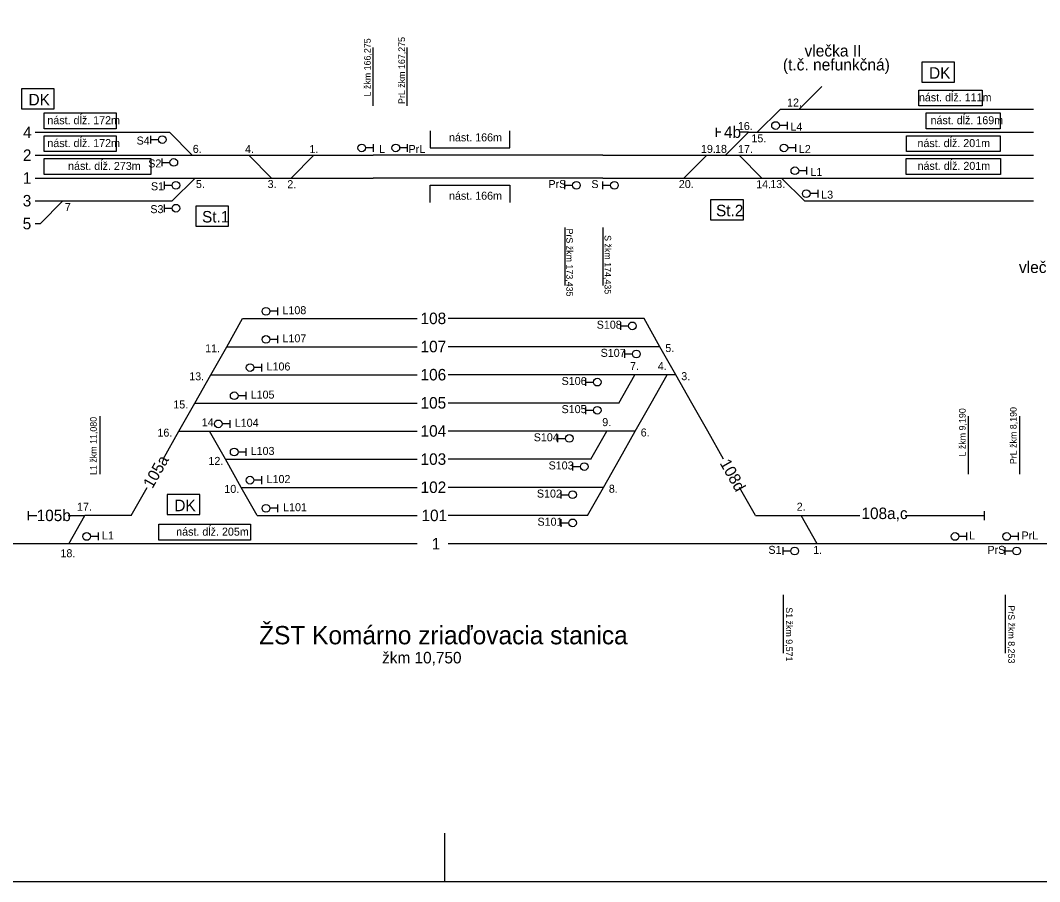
# Model space of a CAD drawing. Extents: x -119 to 851, y -238 to 59.
# Drawn here: x 243.9 to 333.1, y -238 to -162.7 of the extents above; entities that cross this region are included whole.
import ezdxf

# ---------------------------------------------------------------- set-up
doc = ezdxf.new("R2010")
doc.units = 0
for name, color, linetype in [('budova', 7, 'Continuous'), ('Level 2', 7, 'Continuous'), ('nastupistia', 7, 'Continuous'), ('netlač', 7, 'Continuous'), ('popisky navestidla', 7, 'Continuous'), ('popisky stanic a zastavok', 7, 'Continuous'), ('PU_navestidla', 7, 'Continuous'), ('PU_oznacenie navestidiel', 7, 'Continuous'), ('PU_stan_kolaje', 7, 'Continuous'), ('PU_vlecky', 7, 'Continuous')]:
    doc.layers.add(name, color=color, linetype=linetype)

msp = doc.modelspace()

# ---------------------------------------------------------------- linework, layer by layer
at = {"layer": 'budova'}
for points in [[(322.778, -168.11), (325.645, -168.11), (325.645, -166.362), (322.778, -166.362)], [(244.019, -170.441), (246.886, -170.441), (246.886, -168.693), (244.019, -168.693)], [(259.277, -180.699), (262.144, -180.699), (262.144, -178.951), (259.277, -178.951)], [(304.306, -180.156), (307.173, -180.156), (307.173, -178.408), (304.306, -178.408)], [(256.771, -205.924), (259.638, -205.924), (259.638, -204.176), (256.771, -204.176)]]:
    msp.add_lwpolyline(points, close=True, dxfattribs=at)
at = {"layer": 'Level 2'}
for p, q in [((332.55, -170.496), (310.376, -170.496)), ((332.17, -170.496), (331.948, -170.496)), ((245.232, -172.495), (256.972, -172.495)), ((304.823, -172.894), (304.823, -172.095)), ((305.192, -172.495), (304.823, -172.495)), ((307.616, -172.495), (306.853, -172.495)), ((307.616, -172.495), (332.55, -172.495)), ((245.232, -174.494), (252.131, -174.494)), ((252.131, -174.494), (274.8, -174.494)), ((294.882, -174.494), (301.378, -174.494)), ((301.378, -174.494), (317.575, -174.494)), ((317.575, -174.494), (332.55, -174.494)), ((245.232, -176.493), (253.131, -176.493)), ((253.131, -176.493), (271.429, -176.493)), ((271.429, -176.493), (274.8, -176.493)), ((294.882, -176.493), (316.376, -176.493)), ((316.376, -176.493), (332.55, -176.493)), ((245.232, -178.492), (257.207, -178.492)), ((312.507, -178.492), (332.55, -178.492)), ((245.65, -180.491), (245.232, -180.491)), ((244.601, -205.606), (244.601, -206.406)), ((328.225, -205.606), (328.225, -206.406)), ((244.601, -206.006), (245.382, -206.006)), ((248.098, -206.006), (249.564, -206.006)), ((278.636, -208.467), (236.419, -208.467)), ((360.51, -208.467), (281.352, -208.467))]:
    msp.add_line(p, q, dxfattribs=at)
at = {"layer": 'nastupistia'}
for points in [[(328.056, -170.184), (322.513, -170.184), (322.513, -168.799), (328.056, -168.799)], [(252.317, -172.183), (246.022, -172.183), (246.022, -170.798), (252.317, -170.798)], [(329.631, -172.183), (323.147, -172.183), (323.147, -170.798), (329.631, -170.798)], [(252.317, -174.182), (246.022, -174.182), (246.022, -172.797), (252.317, -172.797)], [(329.631, -174.182), (321.428, -174.182), (321.428, -172.797), (329.631, -172.797)], [(255.343, -176.181), (246.019, -176.181), (246.019, -174.796), (255.343, -174.796)], [(329.641, -176.171), (321.417, -176.171), (321.417, -174.786), (329.641, -174.786)], [(264.048, -208.155), (256.05, -208.155), (256.05, -206.77), (264.048, -206.77)]]:
    msp.add_lwpolyline(points, close=True, dxfattribs=at)
for points in [[(279.775, -172.355), (279.775, -173.859), (286.733, -173.859), (286.733, -172.355)], [(279.775, -178.632), (279.775, -177.129), (286.749, -177.129), (286.749, -178.632)]]:
    msp.add_lwpolyline(points, dxfattribs=at)
at = {"layer": 'netlač'}
for p, q in [((294.882, -174.494), (274.8, -174.494)), ((294.882, -176.493), (274.8, -176.493)), ((263.366, -188.78), (278.636, -188.78)), ((298.482, -188.78), (281.352, -188.78)), ((261.975, -191.241), (278.636, -191.241)), ((299.873, -191.241), (281.352, -191.241)), ((260.583, -193.702), (278.636, -193.702)), ((301.264, -193.702), (281.352, -193.702)), ((259.192, -196.162), (278.636, -196.162)), ((296.272, -196.162), (281.352, -196.162)), ((257.801, -198.623), (278.636, -198.623)), ((297.716, -198.623), (281.352, -198.623)), ((261.864, -201.084), (278.636, -201.084)), ((293.833, -201.084), (281.352, -201.084)), ((263.255, -203.545), (278.636, -203.545)), ((294.933, -203.545), (281.352, -203.545)), ((253.626, -206.006), (249.564, -206.006)), ((264.646, -206.006), (278.636, -206.006)), ((293.542, -206.006), (281.352, -206.006)), ((308.221, -206.006), (312.226, -206.006)), ((312.226, -206.006), (317.358, -206.006)), ((321.321, -206.006), (328.225, -206.006))]:
    msp.add_line(p, q, dxfattribs=at)
at = {"layer": 'popisky navestidla'}
for p, q in [((274.8, -170.181), (274.8, -165.091)), ((277.775, -170.181), (277.775, -165.091)), ((291.554, -180.806), (291.554, -185.897)), ((294.882, -180.806), (294.882, -185.897)), ((250.869, -197.303), (250.869, -202.394)), ((326.827, -197.303), (326.827, -202.394)), ((331.331, -197.303), (331.331, -202.394)), ((310.678, -218.037), (310.678, -212.946)), ((330.09, -218.037), (330.09, -212.946)), ((281.049, -238.008), (281.049, -233.772))]:
    msp.add_line(p, q, dxfattribs=at)
msp.add_lwpolyline([(-118.951, -238.008), (851.049, -238.008), (851.049, 58.992), (-118.951, 58.992)], close=True, dxfattribs=at)
at = {"layer": 'PU_navestidla'}
for p, q in [((310.988, -171.903), (310.316, -171.903)), ((310.988, -171.566), (310.988, -172.238)), ((255.331, -173.466), (255.331, -172.795)), ((255.331, -173.129), (256.003, -173.129)), ((274.8, -173.522), (274.8, -174.194)), ((277.775, -173.522), (277.775, -174.194)), ((311.722, -173.522), (311.722, -174.194)), ((274.8, -173.859), (274.128, -173.859)), ((277.775, -173.859), (277.103, -173.859)), ((311.722, -173.859), (311.05, -173.859)), ((256.344, -175.465), (256.344, -174.794)), ((256.344, -175.128), (257.016, -175.128)), ((312.677, -175.521), (312.677, -176.193)), ((312.677, -175.858), (312.005, -175.858)), ((256.53, -177.464), (256.53, -176.793)), ((256.53, -177.127), (257.202, -177.127)), ((291.554, -177.466), (291.554, -176.794)), ((291.554, -177.129), (292.226, -177.129)), ((294.882, -177.466), (294.882, -176.794)), ((294.882, -177.129), (295.554, -177.129)), ((313.676, -177.857), (313.004, -177.857)), ((313.676, -177.52), (313.676, -178.192)), ((256.531, -179.463), (256.531, -178.792)), ((256.531, -179.126), (257.203, -179.126)), ((266.423, -187.808), (266.423, -188.48)), ((266.423, -188.145), (265.751, -188.145)), ((296.452, -189.752), (296.452, -189.08)), ((296.452, -189.414), (297.124, -189.414)), ((266.423, -190.606), (265.751, -190.606)), ((266.423, -190.269), (266.423, -190.941)), ((296.793, -192.213), (296.793, -191.541)), ((296.793, -191.875), (297.465, -191.875)), ((265.031, -193.067), (264.359, -193.067)), ((265.031, -192.73), (265.031, -193.402)), ((293.38, -194.674), (293.38, -194.002)), ((263.64, -195.19), (263.64, -195.862)), ((293.38, -194.336), (294.052, -194.336)), ((263.64, -195.528), (262.968, -195.528)), ((293.38, -197.134), (293.38, -196.462)), ((293.38, -196.797), (294.052, -196.797)), ((262.248, -197.651), (262.248, -198.323)), ((262.248, -197.989), (261.576, -197.989)), ((290.94, -199.595), (290.94, -198.923)), ((290.94, -199.258), (291.612, -199.258)), ((263.64, -200.45), (262.968, -200.45)), ((263.64, -200.112), (263.64, -200.784)), ((292.242, -202.056), (292.242, -201.384)), ((292.242, -201.719), (292.914, -201.719)), ((265.031, -202.911), (264.359, -202.911)), ((265.031, -202.573), (265.031, -203.245)), ((291.218, -204.517), (291.218, -203.845)), ((291.218, -204.18), (291.89, -204.18)), ((266.423, -205.371), (265.751, -205.371)), ((266.423, -205.034), (266.423, -205.706)), ((291.218, -206.978), (291.218, -206.306)), ((291.218, -206.641), (291.89, -206.641)), ((250.736, -207.495), (250.736, -208.167)), ((326.694, -207.495), (326.694, -208.167)), ((331.198, -207.495), (331.198, -208.167)), ((250.736, -207.832), (250.064, -207.832)), ((326.694, -207.832), (326.022, -207.832)), ((331.198, -207.832), (330.526, -207.832)), ((310.649, -209.439), (310.649, -208.767)), ((310.649, -209.102), (311.321, -209.102)), ((330.061, -209.439), (330.061, -208.767)), ((330.061, -209.102), (330.733, -209.102))]:
    msp.add_line(p, q, dxfattribs=at)
for centre in [(309.98, -171.902), (256.339, -173.131), (273.792, -173.857), (276.767, -173.857), (310.714, -173.857), (257.352, -175.13), (311.669, -175.856), (257.538, -177.129), (292.562, -177.13), (295.89, -177.13), (312.668, -177.855), (257.539, -179.128), (265.415, -188.144), (297.46, -189.416), (265.415, -190.605), (297.801, -191.877), (264.023, -193.066), (294.388, -194.338), (262.632, -195.526), (294.388, -196.798), (261.24, -197.987), (291.948, -199.259), (262.632, -200.448), (293.25, -201.72), (264.023, -202.909), (292.226, -204.181), (265.415, -205.37), (292.226, -206.642), (249.728, -207.831), (325.686, -207.831), (330.19, -207.831), (311.657, -209.103), (331.069, -209.103)]:
    msp.add_circle(centre, 0.336, dxfattribs=at)
at = {"layer": 'PU_stan_kolaje'}
for points in [[(314.017, -168.497), (312.018, -170.496)], [(310.376, -170.496), (308.377, -172.495)], [(256.972, -172.495), (258.971, -174.494)], [(307.616, -172.495), (305.617, -174.494)], [(263.902, -174.494), (265.901, -176.493)], [(269.611, -174.494), (267.612, -176.493)], [(303.961, -174.494), (301.962, -176.493)], [(306.796, -174.494), (308.795, -176.493)], [(259.206, -176.493), (257.207, -178.492)], [(310.508, -176.493), (312.505, -178.49)], [(247.649, -178.492), (245.65, -180.491)], [(261.975, -191.241), (263.366, -188.78)], [(299.873, -191.241), (298.482, -188.78)], [(260.583, -193.702), (261.975, -191.241)], [(301.264, -193.702), (299.873, -191.241)], [(259.192, -196.162), (260.583, -193.702)], [(296.272, -196.162), (297.664, -193.702)], [(299.107, -196.162), (300.499, -193.702)], [(302.656, -196.162), (301.264, -193.702)], [(257.801, -198.623), (259.192, -196.162)], [(297.716, -198.623), (299.107, -196.162)], [(304.047, -198.623), (302.656, -196.162)], [(256.409, -201.084), (257.801, -198.623)], [(261.864, -201.084), (260.472, -198.623)], [(293.833, -201.084), (295.224, -198.623)], [(296.325, -201.084), (297.716, -198.623)], [(305.439, -201.084), (304.047, -198.623)], [(263.255, -203.545), (261.864, -201.084)], [(294.933, -203.545), (296.325, -201.084)], [(253.626, -206.006), (255.018, -203.545)], [(264.646, -206.006), (263.255, -203.545)], [(293.542, -206.006), (294.933, -203.545)], [(308.221, -206.006), (306.83, -203.545)], [(248.172, -208.467), (249.564, -206.006)], [(313.618, -208.467), (312.226, -206.006)]]:
    msp.add_lwpolyline(points, dxfattribs=at)

# ---------------------------------------------------------------- texts
at = {"layer": 'budova'}
for s, p in [('DK', (323.407, -167.806)), ('DK', (244.648, -170.137)), ('St.2', (304.774, -179.835)), ('St.1', (259.822, -180.378)), ('DK', (257.4, -205.62))]:
    msp.add_text(s, height=1.0044, dxfattribs=at).set_placement(p)
at = {"layer": 'nastupistia'}
for s, p in [('nást. dĺž. 111m', (322.52, -169.789)), ('nást. dĺž. 172m', (246.295, -171.788)), ('nást. dĺž. 169m', (323.538, -171.788)), ('nást. dĺž. 172m', (246.295, -173.787)), ('nást. 166m', (281.423, -173.287)), ('nást. dĺž. 201m', (322.393, -173.787)), ('nást. dĺž. 273m', (248.105, -175.786)), ('nást. dĺž. 201m', (322.403, -175.777)), ('nást. 166m', (281.423, -178.389)), ('nást. dĺž. 205m', (257.558, -207.761))]:
    msp.add_text(s, height=0.7, dxfattribs=at).set_placement(p)
at = {"layer": 'popisky navestidla'}
for s, rotation, p in [('L žkm 166,275', 90, (274.572, -169.361)), ('PrL žkm 167,275 ', 90, (277.573, -170.018)), ('PrS žkm 173,435', 270, (291.683, -180.908)), ('S žkm 174,435', 270, (295.022, -181.483)), ('L žkm 9,190', 90, (326.608, -200.843)), ('PrL žkm 8,190', 90, (331.066, -201.51)), ('L1 žkm 11,080', 90, (250.612, -202.456)), ('PrS žkm 8,253', 270, (330.327, -213.851)), ('S1 žkm 9,571', 270, (310.888, -214.021))]:
    msp.add_text(s, height=0.57931, rotation=rotation, dxfattribs=at).set_placement(p)
at = {"layer": 'popisky stanic a zastavok'}
for s, height, p in [('ŽST Komárno zriaďovacia stanica', 1.6, (264.814, -217.261)), ('žkm 10,750', 1.0044, (275.571, -218.929))]:
    msp.add_text(s, height=height, dxfattribs=at).set_placement(p)
at = {"layer": 'PU_oznacenie navestidiel'}
for s, p in [('12.', (310.988, -170.241)), ('16.', (306.686, -172.297)), ('L4', (311.287, -172.352)), ('S4', (254.099, -173.566)), ('15.', (307.872, -173.369)), ('6.', (259.011, -174.296)), ('4.', (263.582, -174.307)), ('1.', (269.215, -174.307)), ('L', (275.318, -174.307)), ('PrL', (277.887, -174.307)), ('19.', (303.456, -174.296)), ('18.', (304.687, -174.296)), ('17.', (306.697, -174.307)), ('L2', (312.023, -174.307)), ('S2', (255.114, -175.565)), ('L1', (313.031, -176.306)), ('S1', (255.353, -177.564)), ('5.', (259.288, -177.367)), ('3.', (265.558, -177.367)), ('2.', (267.279, -177.379)), ('PrS', (290.119, -177.368)), ('S', (293.873, -177.368)), ('20.', (301.521, -177.367)), ('14.', (308.29, -177.379)), ('13.', (309.522, -177.367)), ('L3', (313.974, -178.294)), ('7', (247.822, -179.378)), ('S3', (255.298, -179.563)), ('L108', (266.856, -188.397)), ('S108', (294.34, -189.666)), ('L107', (266.857, -190.858)), ('11.', (260.094, -191.73)), ('S107', (294.682, -192.127)), ('5.', (300.342, -191.705)), ('L106', (265.466, -193.318)), ('7.', (297.258, -193.276)), ('4.', (299.684, -193.276)), ('13.', (258.703, -194.179)), ('S106', (291.269, -194.588)), ('3.', (301.734, -194.166)), ('L105', (264.072, -195.779)), ('15.', (257.311, -196.64)), ('S105', (291.266, -197.048)), ('14.', (259.795, -198.198)), ('L104', (262.684, -198.24)), ('9.', (294.824, -198.186)), ('16.', (255.92, -199.101)), ('6.', (298.189, -199.088)), ('S104', (288.83, -199.509)), ('L103', (264.075, -200.701)), ('12.', (260.381, -201.574)), ('S103', (290.131, -201.97)), ('L102', (265.468, -203.162)), ('10.', (261.772, -204.023)), ('S102', (289.109, -204.431)), ('8.', (295.402, -204.009)), ('17.', (248.886, -205.58)), ('L101', (266.913, -205.623)), ('2.', (311.835, -205.58)), ('S101', (289.162, -206.892)), ('L1', (251.067, -208.096)), ('L', (326.903, -208.096)), ('PrL', (331.497, -208.096)), ('18.', (247.438, -209.646)), ('S1', (309.358, -209.353)), ('1.', (313.275, -209.365)), ('PrS', (328.513, -209.353))]:
    msp.add_text(s, height=0.7, dxfattribs=at).set_placement(p)
at = {"layer": 'PU_stan_kolaje'}
for s, height, p in [('4', 1.004, (244.172, -172.997)), ('4b', 1.0044, (305.468, -172.98)), ('2', 1.004, (244.156, -174.996)), ('1', 1.004, (244.141, -176.995)), ('3', 1.004, (244.139, -178.977)), ('5', 1.004, (244.136, -180.976)), ('108', 1.0044, (278.934, -189.265)), ('107', 1.0044, (278.935, -191.726)), ('106', 1.0044, (278.935, -194.187)), ('105', 1.0044, (278.932, -196.648)), ('104', 1.0044, (278.936, -199.108)), ('103', 1.0044, (278.935, -201.569)), ('102', 1.0044, (278.938, -204.03)), ('105b', 1.0044, (245.357, -206.491)), ('101', 1.0044, (279.014, -206.491)), ('108a,c', 1.0044, (317.497, -206.31)), ('1', 1.004, (279.905, -208.969))]:
    msp.add_text(s, height=height, dxfattribs=at).set_placement(p)
for s, rotation, p in [('105a', 60.51592, (255.483, -203.707)), ('108d', 299.48408, (305.068, -201.414))]:
    msp.add_text(s, height=1.0044, rotation=rotation, dxfattribs=at).set_placement(p)
at = {"layer": 'PU_vlecky'}
for s, p in [('vlečka II', (312.514, -165.867)), ('(t.č. nefunkčná)', (310.623, -167.085)), ('vlečka Gamex Trading', (331.27, -184.796))]:
    msp.add_text(s, height=1.015, dxfattribs=at).set_placement(p)

doc.saveas('drawing.dxf')
